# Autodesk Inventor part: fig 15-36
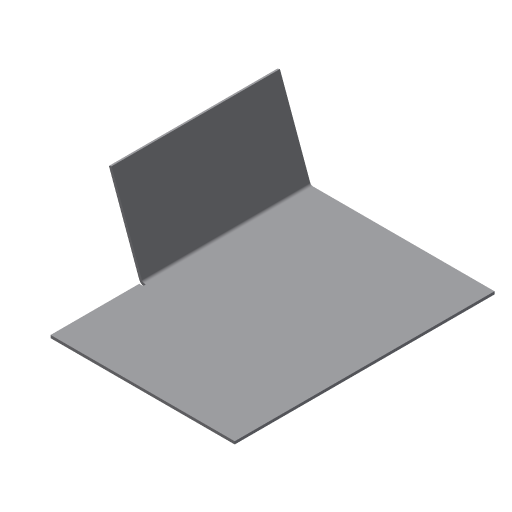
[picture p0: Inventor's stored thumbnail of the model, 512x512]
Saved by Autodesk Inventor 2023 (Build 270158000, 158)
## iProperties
Created: 2005-03
Part Number: fig 15-36
Document SubType Name: Sheet Metal
Designer: CADCIM
Manufacturer: Standard
Standards Organization: Custom
Density: 1 g/cm^3
Sheet Metal Rule: Default
Material: Generic
Appearance: Default
Author: CADCIM
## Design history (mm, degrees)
node "Face1"
  sketch "Sketch1"
    geometry: L1 (31.393, 35.714)-(-17.775, 35.714); L2 (-17.775, 35.714)-(-17.775, 5.625); L3 (-17.775, 5.625)-(-1.5, 5.625); L4 (-1.5, 5.625)-(-1.5, -10.705); L5 (-1.5, -10.705)-(31.393, -10.705); L6 (31.393, -10.705)-(31.393, 35.714)
    constraints: 12 end point, 4 parallel, 1 horizontal, 1 perpendicular
sketch "Sketch3"
  geometry: L1 (16.275, -30.089)-(16.275, 0); L2 (16.275, -46.42)-(16.275, -30.089) reference; L3 (16.275, -30.089)-(0, -30.089) reference; L4 (0, 0)-(49.168, 0) reference
  constraints: 3 point on line, 2 end point, 1 vertical
feature "Fold1" sketch "Sketch3" dims "d1" = 0.5 (= BendReliefWidth), "d2" = 0.25 (= BendReliefDepth), "d3" = 1 (= MinimumRemnant), "d4" = 0.5 (= BendRadius), "d5" = 70 deg, "d6" = 0.5 (= BendRadius), "d7" = 0.5 (= Thickness), "SeamGap" = 0.01
body "Solid1"
face "Plate1" dims "d7" = 0.5 (= Thickness)
other parameters: "Thickness" = 0.5, "BendRadius" = 0.5 (= Thickness), "BendReliefWidth" = 0.5 (= Thickness), "BendReliefDepth" = 0.25 (= 0.5 x Thickness), "CornerReliefSize" = 2 (= 4 x Thickness), "MinimumRemnant" = 1 (= 2 x Thickness), "TransitionRadius" = 0.5 (= BendRadius), "d0" = 0.5 (= BendRadius), "JacobiRadiusSize" = 0.5 (= Thickness), "GapSize" = 0.5 (= Thickness)
